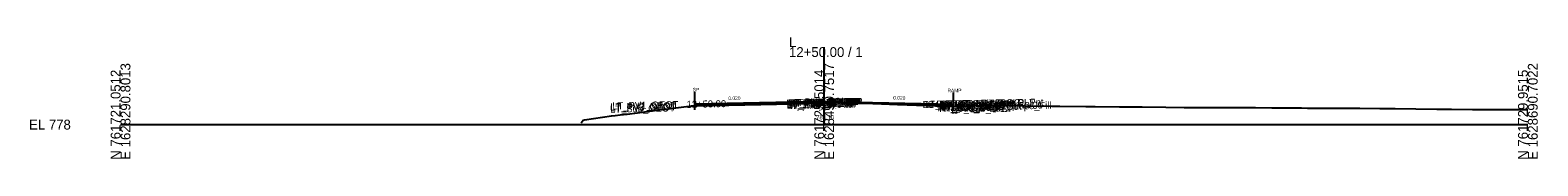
# Model space of a CAD drawing. Extents: x -26 to 4403, y -510 to 9556.
# Drawn here: x -25.7 to 402.8, y 2490.3 to 2524.8 of the extents above; entities that cross this region are included whole.
import ezdxf

# ---------------------------------------------------------------- set-up
doc = ezdxf.new("R2010")
doc.units = 0
for name, color, linetype in [('Default', 7, 'Continuous'), ('Exist CMT Pavement', 7, 'Continuous'), ('Exist Cross Section Cell', 7, 'Continuous'), ('Exist XS Center Line Elevation Label', 7, 'Continuous'), ('Exist XS Ground Line', 7, 'Continuous'), ('Prop CMT Pvmt Course 1', 7, 'Continuous'), ('Prop CMT Pvmt Course 2', 7, 'Continuous'), ('Prop CMT Pvmt Surface', 7, 'Continuous'), ('Prop CMT Shear Line', 7, 'Continuous'), ('Prop XS Hydro Elevations', 7, 'Continuous'), ('Prop XS SE Text', 7, 'Continuous'), ('Scratch_Level_0', 7, 'Continuous')]:
    doc.layers.add(name, color=color, linetype=linetype)

msp = doc.modelspace()

# ---------------------------------------------------------------- linework, layer by layer
at = {"layer": 'Exist CMT Pavement'}
for p, q in [((163.25, 2505.36), (163.93, 2505.38)), ((163.93, 2505.38), (181.96, 2505.74)), ((181.96, 2505.74), (200, 2506.1)), ((200, 2506.1), (203.46, 2506.17)), ((203.46, 2506.17), (207.24, 2506.25)), ((207.24, 2506.25), (220.79, 2505.76)), ((220.79, 2505.76), (234.34, 2505.27)), ((234.34, 2505.27), (235.38, 2505.26)), ((235.38, 2505.26), (235.82, 2505.25)), ((235.82, 2505.25), (236.37, 2505.25)), ((236.37, 2505.25), (236.53, 2505.25)), ((236.53, 2505.25), (236.75, 2505.25))]:
    msp.add_line(p, q, dxfattribs=at)
at = {"layer": 'Exist Cross Section Cell'}
for p, q in [((200, 2500), (200, 2522.02)), ((0, 2500), (200, 2500)), ((200, 2500), (400, 2500))]:
    msp.add_line(p, q, dxfattribs=at)
at = {"layer": 'Exist XS Ground Line'}
msp.add_lwpolyline([(130.88, 2500.54), (131.53, 2501.25), (131.9, 2501.32), (139.57, 2502.47), (140.62, 2502.59), (142.01, 2502.75), (143.96, 2503), (146.89, 2503.36), (151.79, 2503.99), (161.64, 2505.26), (162.24, 2505.34), (163.93, 2505.38), (200, 2506.1), (206.91, 2506.24), (207.24, 2506.25), (234.34, 2505.27), (235.38, 2505.26), (236.27, 2505.25), (236.8, 2505.25), (239.78, 2505.24), (240.38, 2505.24), (241.61, 2505.52), (242.2, 2505.51), (242.61, 2505.51), (244.95, 2505.48), (251.21, 2505.42), (256.89, 2505.36), (264.66, 2505.28), (266.94, 2505.26), (274.32, 2505.19), (276.99, 2505.16), (283.97, 2505.09), (287.03, 2505.06), (290.36, 2505.02), (297.08, 2504.96), (302.28, 2504.9), (305.45, 2504.87), (306.12, 2504.86), (307.13, 2504.86), (312.93, 2504.86), (317.18, 2504.82), (322.58, 2504.82), (327.23, 2504.77), (330.64, 2504.76), (333.98, 2504.73), (335.66, 2504.73), (337.36, 2504.71), (342.77, 2504.64), (347.64, 2504.64), (352.23, 2504.63), (357.89, 2504.56), (362.26, 2504.55), (368.12, 2504.48), (374.09, 2504.41), (378.34, 2504.4), (384.3, 2504.33), (388.56, 2504.32), (392.9, 2504.32), (398.79, 2504.25), (400, 2504.25)], dxfattribs=at)
at = {"layer": 'Prop CMT Pvmt Course 1'}
for points in [[(200, 2506.53), (163.25, 2505.79)], [(163.25, 2505.54), (200, 2506.28)], [(200, 2506.28), (200, 2506.53)], [(200, 2506.53), (236.75, 2505.79)], [(200, 2506.28), (200, 2506.53)], [(200, 2506.28), (200, 2506.4)], [(200, 2506.4), (200, 2506.4)], [(200, 2506.4), (200, 2506.28)], [(200, 2506.28), (200, 2506.4)], [(200, 2506.4), (200, 2506.4)], [(200, 2506.4), (200, 2506.28)], [(200, 2506.28), (200, 2506.28)], [(236.75, 2505.54), (200, 2506.28)], [(200, 2506.28), (200, 2506.28)]]:
    msp.add_lwpolyline(points, dxfattribs=at)
at = {"layer": 'Prop CMT Pvmt Course 2'}
for points in [[(200, 2506.28), (163.25, 2505.54)], [(200, 2506.28), (236.75, 2505.54)]]:
    msp.add_lwpolyline(points, dxfattribs=at)
at = {"layer": 'Prop CMT Pvmt Surface'}
for points in [[(200, 2506.53), (163.25, 2505.79)], [(200, 2506.53), (236.75, 2505.79)]]:
    msp.add_lwpolyline(points, dxfattribs=at)
at = {"layer": 'Prop CMT Shear Line'}
for p, q in [((163.25, 2504.24), (163.25, 2509.36)), ((236.75, 2503.99), (236.75, 2509.1))]:
    msp.add_line(p, q, dxfattribs=at)

# ---------------------------------------------------------------- texts
at = {"layer": 'Default'}
msp.add_text('-', height=0.0001, dxfattribs=at).set_placement((0, 2500))
at = {"layer": 'Exist Cross Section Cell'}
for s, p in [('L', (190, 2522.02)), ('12+50.00 / 1', (190, 2519.22)), ('EL 778', (-26, 2498.6))]:
    msp.add_text(s, height=2.8, dxfattribs=at).set_placement(p)
for s, p in [('E 1628290.8013', (2.8, 2490)), ('N 761725.5014', (200, 2490)), ('E 1628490.7517', (202.8, 2490)), ('E 1628690.7022', (402.8, 2490)), ('N 761721.0512', (0, 2490)), ('N 761729.9515', (400, 2490))]:
    msp.add_text(s, height=2.8, rotation=90, dxfattribs=at).set_placement(p)
at = {"layer": 'Exist XS Center Line Elevation Label'}
msp.add_text('784.10', height=1.2, dxfattribs=at).set_placement((197.74, 2501.5))
at = {"layer": 'Prop XS Hydro Elevations'}
for s, p in [('SP', (162.62, 2509.45)), ('RAMP', (235.03, 2509.19))]:
    msp.add_text(s, height=1, rotation=360, dxfattribs=at).set_placement(p)
at = {"layer": 'Prop XS SE Text'}
for rotation, p in [(1.1458, (172.76, 2506.98)), (358.8549, (219.61, 2507.14))]:
    msp.add_text('0.020', height=1, rotation=rotation, dxfattribs=at).set_placement(p)
at = {"layer": 'Scratch_Level_0'}
for s, p in [('12+50.00', (160.92, 2504.75)), ('RT_PV2_OEEOP', (189.28, 2505.06)), ('RT_PV3_OEEOP', (189.28, 2504.73)), ('LT_PV2_OEEOP', (189.33, 2505.06)), ('LT_PV3_OEEOP', (189.33, 2504.73)), ('RT_PV1_OEEOP', (189.85, 2505.2)), ('LT_PV1_OEEOP', (189.89, 2505.2)), ('RT_PV2_IEEOP', (189.93, 2505.08)), ('LT_PV2_IEEOP', (189.98, 2505.08)), ('RT_PV1_IEEOP', (190.49, 2505.21)), ('LT_PV1_IEEOP', (190.54, 2505.21)), ('PV2_PGL', (193.93, 2505.16)), ('PV1_PGL', (194.49, 2505.42)), ('RT_Sub_Trench_Out_DLT', (227.97, 2504.71)), ('12+50.00', (228.25, 2504.72)), ('RT_CG_Top_Face', (231.91, 2504.8)), ('RT_CG_Top_BOC', (233.43, 2504.82)), ('12+50.00', (238.75, 2504.93)), ('RT_CSLP_Pnt', (244.82, 2505.05)), ('LT_Sub_OEOT', (139.15, 2503.39)), ('LT_PV2_OEOT', (139.25, 2504.06)), ('LT_PV3_OEOT', (139.25, 2503.73)), ('LT_PV1_OEOT', (139.82, 2504.32)), ('RT_Sub_OEEOP', (189.19, 2504.39)), ('LT_Sub_OEEOP', (189.23, 2504.4)), ('RT_CG1_Shelf_Out', (232.2, 2503.76)), ('RT_CG_Bot_IE', (232.56, 2503.89)), ('RT_Sub_OEOT', (232.73, 2503.56)), ('RT_PV2_OEOT', (232.82, 2504.23)), ('RT_PV3_OEOT', (232.82, 2503.89)), ('RT_CG_Top_Gut', (232.88, 2504.32)), ('RT_PV1_OEOT', (233.39, 2504.49)), ('RT_CG_Bot_BOC', (233.46, 2503.81)), ('RT_Sub_OEOP', (236.1, 2503.49)), ('12+50.00', (236.89, 2504.53)), ('RT_Slope_Fill', (247.82, 2504.17)), ('12+50.00', (250.94, 2504.31))]:
    msp.add_text(s, height=2, rotation=1.1458, dxfattribs=at).set_placement(p)

doc.saveas('drawing.dxf')
